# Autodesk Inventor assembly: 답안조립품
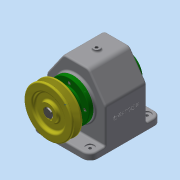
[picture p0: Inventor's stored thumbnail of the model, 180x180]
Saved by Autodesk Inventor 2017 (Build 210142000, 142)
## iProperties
Part Number: 답안조립품
Material: 일반
Document SubType Name: Assembly
Designer: MRC
Author: MRC
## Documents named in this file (15)
- C:\Users\MRC\Desktop\721206V1006\답안조립품.iam
- C:\Users\MRC\Desktop\721206V1006\본체.ipt
- C:\Users\MRC\Desktop\721206V1006\축.ipt
- C:\Users\MRC\Desktop\721206V1006\베어링 6203.ipt
- C:\Users\MRC\Desktop\721206V1006\뒤커버.ipt
- C:\Users\MRC\Desktop\721206V1006\앞커버.ipt
- C:\Users\MRC\Desktop\721206V1006\키 - 6 x 6 x 22.ipt
- C:\Users\MRC\Desktop\721206V1006\스퍼기어.ipt
- C:\Users\MRC\Desktop\721206V1006\칼라.ipt
- C:\Users\MRC\Desktop\721206V1006\오일 실 17 x 32 x 8.ipt
- C:\Users\MRC\Desktop\721206V1006\볼트 M3 x 8.ipt
- C:\Users\MRC\Desktop\721206V1006\볼트 M3 x 10.ipt
- C:\Users\MRC\Desktop\721206V1006\키 - 5 x 5 x 18.ipt
- C:\Users\MRC\Desktop\721206V1006\V-벨트풀리.ipt
- C:\Users\MRC\Desktop\721206V1006\멈춤나사 - M4x10.ipt
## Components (9 placed, 3 different names)
1. V-벨트풀리:1
2. ISO 4762 M3 x 8:1
3. ISO 4762 M3 x 8:2
4. ISO 4762 M3 x 8:3
5. ISO 4762 M3 x 8:4
6. ISO 4762 M3 x 10:1
7. ISO 4762 M3 x 10:2
8. ISO 4762 M3 x 10:3
9. ISO 4762 M3 x 10:4
